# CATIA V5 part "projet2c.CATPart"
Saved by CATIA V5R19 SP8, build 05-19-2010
Part number: projet2c
Bounding box of the stored display mesh (mm): x -121.195 to 10, y -156.666 to 15, z 0 to 100
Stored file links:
  C:\Documents and Settings\msamadi\Bureau\projet 2 vendredi\projet2c.CATPart
  C:\Documents and Settings\msamadi\Bureau\Nouveau dossier\Product1.CATProduct
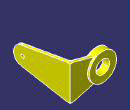
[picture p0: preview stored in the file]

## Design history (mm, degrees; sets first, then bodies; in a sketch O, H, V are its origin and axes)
Parameters
  LENGTH = 10 mm
Set1
  Point1: (0 {= LENGTH *0}, 15 {= LENGTH *1.5}, 25 {= LENGTH *2.5})
  Plane1: type OffsetPt, RefPlane end face of Pad2, RefPoint Point1
Body1 (main body)
  Sketch1 on yz-plane, origin (0, 0, 0), H (0, 1, 0), V (0, 0, 1)
    line L1 (0, 0) -> (0, 100)
    point P1 (0, 100)
    point P2 (0, 100)
    line L2 (0, 100) -> (-134.6305, 76.261)
    line L3 (-134.6305, 23.739) -> (0, 0)
    point P5 (0, 0)
    arc A1 centre (-130, 50) radius 26.6661 from (-134.6305, 76.261) to (-134.6305, 23.739) ccw
    point P6 (-130, 50)
    length L1 = 100 {= LENGTH *10}
    angle L2 L1 = 80
    angle L3 L1 = 80
    distance P6 L1 = 130 {= LENGTH *13}
    vertical: L1 V
    tangency: L2 A1, A1 L3
    coincidence: P2 P1, P5 O
  Pad1: profile Sketch1, direction (1, 0, 0), length 10 {= LENGTH *1}
  Sketch2 on end face of Pad1, origin (10, 0, 0), H (0, 1, 0), V (0, 0, 1)
    circle A1 centre (-130, 50) radius 5
    point P1 (-130, 50)
    reference projected arc E1 centre (-130, 50) radius 26.6661 from (-136.9017, 75.7575) to (-136.9017, 24.2425) ccw from edge [face of Pad1 from Sketch1.A1 | end face of Pad1]
    distance P1 A1 = 5 {= LENGTH *0.5}
    concentricity: A1 E1
  Pocket1: profile Sketch2, direction (-1, 0, 0), through (limit type 6), offset 0 {= LENGTH *0}
  Sketch3 on face of Pad1 from Sketch1.L1, origin (0, 0, 0), H (-1, 0, 0), V (0, 0, 1)
    line L1 (0, 100) -> (60, 83.923)
    line L2 (60, 83.923) -> (60, 16.077)
    line L3 (60, 16.077) -> (0, 0)
    point P4 (0, 0)
    line L4 (0, 100) -> (-10, 100)
    line L5 (-10, 100) -> (-10, 0)
    point P6 (-10, 0)
    line L6 (-10, 0) -> (0, 0)
    reference projected line E1 (0, 0) -> (0, 50) from edge [start face of Pad1 | face of Pad1 from Sketch1.L1]
    reference projected line E2 (0, 0) -> (0, 50) from edge [start face of Pad1 | face of Pad1 from Sketch1.L1]
    reference projected line E3 (0, 0) -> (0, 50) from edge [start face of Pad1 | face of Pad1 from Sketch1.L1]
    reference projected line E4 (0, 100) -> (-5, 100) from edge [face of Pad1 from Sketch1.L2 | face of Pad1 from Sketch1.L1]
    reference projected line E5 (-10, 0) -> (-10, 50) from edge [face of Pad1 from Sketch1.L1 | end face of Pad1]
    length L4 = 10 {= LENGTH *1}
    angle L3 E1 = 75
    angle L1 E2 = 75
    distance L2 E3 = 60 {= LENGTH *6}
    vertical: L2 V, L5 V
    coincidence: P4 O, P6 H, L4 E4, E5 L5
    horizontal: L4 H, L6 H
  Pad2: profile Sketch3, direction (0, 1, 0), length 10 {= LENGTH *1}
  Sketch4 on end face of Pad2, origin (0, 10, 0), H (-1, 0, 0), V (0, 0, 1)
    arc A1 centre (81.195, 50) radius 40 from (60, 16.077) to (60, 83.923) cw
    point P1 (60, 16.077)
    point P2 (60, 83.923)
    reference projected point E1 (60, 83.923) from vertex [end face of Pad2 | face of Pad2 from Sketch3.L2 | face of Pad2 from Sketch3.L1]
    reference projected point E2 (60, 16.077) from vertex [face of Pad2 from Sketch3.L2 | face of Pad2 from Sketch3.L3 | end face of Pad2]
    radius A1 = 40 {= LENGTH *4}
    coincidence: P2 E1, P1 E2
  Pocket2: profile Sketch4, direction (0, -1, 0), through (limit type 6), offset 0 {= LENGTH *0}
  Sketch5 on Plane1, origin (0, 15, 0), H (1, 0, 0), V (0, 0, 1)
    circle A1 centre (-81.195, 50) radius 40
    reference projected arc E1 centre (-81.195, 50) radius 40 from (-42.2029, 41.077) to (-42.2029, 58.923) ccw from edge [face of Pocket2 from Sketch4.A1 | start face of Pad2]
    coincidence: A1 E1
  Pad3: profile Sketch5, direction (0, -1, 0), length 20 {= LENGTH *2}
  Sketch6 on start face of Pad3, origin (-82.2312, 15, 49.3301), H (1, 0, 0), V (0, 0, -1)
    point P1 (1.0362, -0.6699)
    reference projected circle E1 centre (1.0362, -0.6699) radius 40 from edge [start face of Pad3 | face of Pad3 from Sketch5.A1]
    concentricity: P1 E1
  Hole1: placed by Sketch6, at (-81.195, 15, 50) direction (0, -1, 0), diameter 40 {= LENGTH *4}, through (limit type 6), offset 0 {= LENGTH *0}
  Fillet1: radius 2 {= LENGTH *0.2}, on edge [start face of Pad1 | face of Pad1 from Sketch1.L3]
  Fillet2: radius 2 {= LENGTH *0.2}, on edge [start face of Pad2 | face of Pad2 from Sketch3.L3]
  Fillet3: radius 2 {= LENGTH *0.2}, on edge [start face of Pad2 | face of Pad2 from Sketch3.L1]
